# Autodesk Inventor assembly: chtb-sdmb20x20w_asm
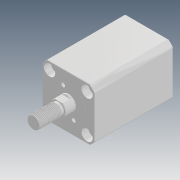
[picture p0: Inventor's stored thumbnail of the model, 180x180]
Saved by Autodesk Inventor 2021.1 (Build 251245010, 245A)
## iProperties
Company: Microsoft
Created: 2018-05
Part Number: chtb-sdmb20x20w_asm
Description: STEP AP214
Document SubType Name: Assembly
Designer: user
Title: chtb-sdmb20x20w_asm.STEP
Author: Windows
Revision Number: ÈÎºÎ
Sending System: SolidWorks 2015
Preprocessor: SwSTEP 2.0
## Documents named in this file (4)
- D:\Vault_2016\Projekty\Clamptek\Hydraulic\CHTB\CHTB-20\Inventor\CHTB-SDMB20x20W\chtb-sdmb20x20w_asm.iam
- D:\Vault_2016\Projekty\Clamptek\Hydraulic\CHTB\CHTB-20\Inventor\CHTB-SDMB20x20W\CHTB-SDMB20X20NBT.ipt
- D:\Vault_2016\Projekty\Clamptek\Hydraulic\CHTB\CHTB-20\Inventor\CHTB-SDMB20x20W\CHTB-SDMB20X20WHSG.ipt
- D:\Vault_2016\Projekty\Clamptek\Hydraulic\CHTB\CHTB-20\Inventor\CHTB-SDMB20x20W\QG_3.ipt
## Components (3 placed, 3 different names)
1. CHTB-SDMB20X20NBT_1
2. CHTB-SDMB20X20WHSG_2
3. QG_3_3
